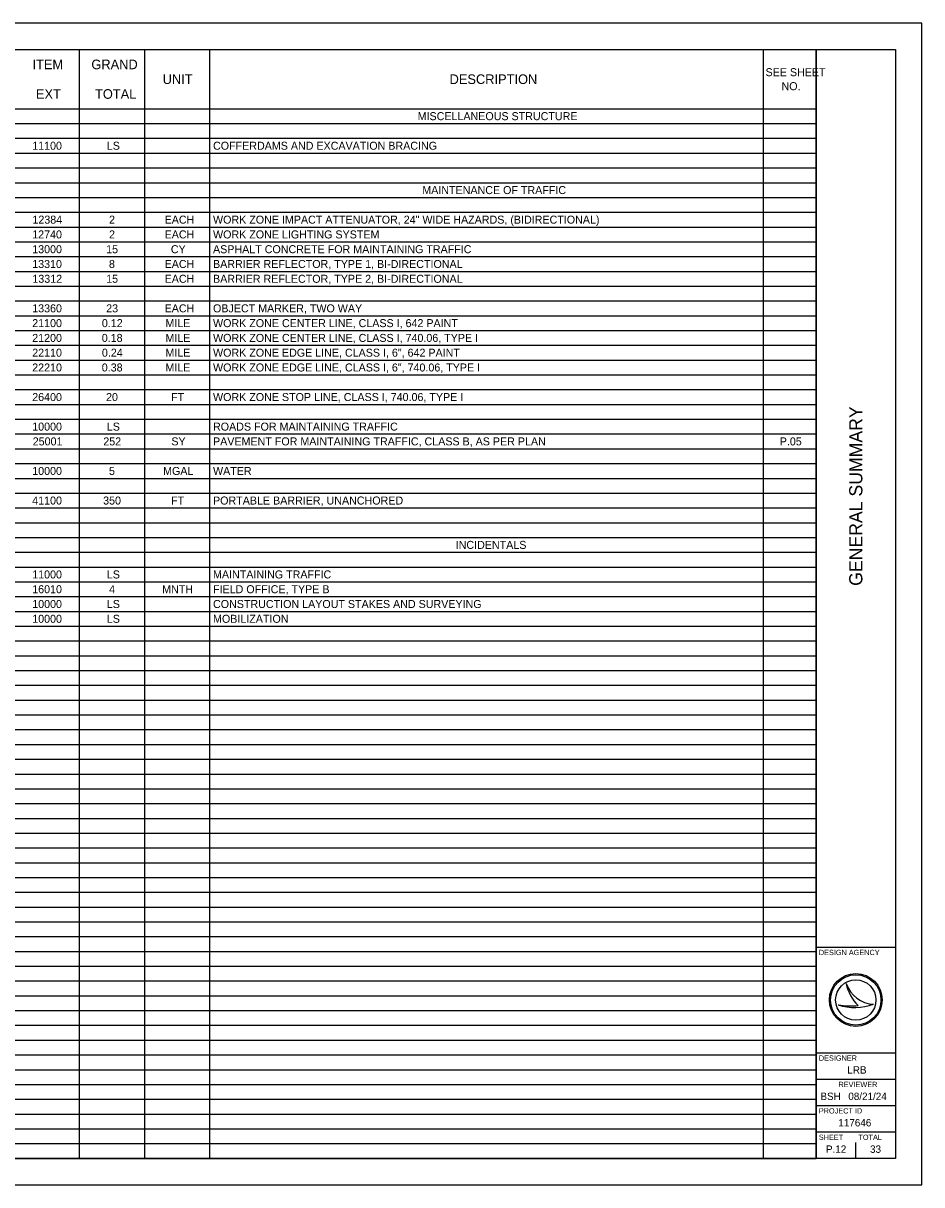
# Model space of a CAD drawing. Extents: x 0 to 34, y 0 to 22.
# Drawn here: x 16.97 to 34, y 0 to 22 of the extents above; entities that cross this region are included whole.
import ezdxf

# ---------------------------------------------------------------- set-up
doc = ezdxf.new("R2010")
doc.units = 0
for name, color, linetype in [('Default', 7, 'Continuous'), ('SH_Border', 7, 'Continuous'), ('SH_Cut_Line', 7, 'Continuous'), ('SH_Data', 7, 'Continuous')]:
    doc.layers.add(name, color=color, linetype=linetype)

msp = doc.modelspace()

# ---------------------------------------------------------------- linework, layer by layer
at = {"layer": 'Default'}
for p, q in [((1.5, 21.5), (32, 21.5)), ((18.035, 21.5), (18.035, 0.5)), ((19.27, 21.5), (19.27, 0.5)), ((20.505, 21.5), (20.505, 0.5)), ((30.995, 21.5), (30.995, 0.5)), ((32, 21.5), (32, 0.5)), ((1.5, 20.38), (32, 20.38)), ((1.5, 20.1), (32, 20.1)), ((1.5, 19.82), (32, 19.82)), ((1.5, 19.54), (32, 19.54)), ((1.5, 19.26), (32, 19.26)), ((1.5, 18.98), (32, 18.98)), ((1.5, 18.7), (32, 18.7)), ((1.5, 18.42), (32, 18.42)), ((1.5, 18.14), (32, 18.14)), ((1.5, 17.86), (32, 17.86)), ((1.5, 17.58), (32, 17.58)), ((1.5, 17.3), (32, 17.3)), ((1.5, 17.02), (32, 17.02)), ((1.5, 16.74), (32, 16.74)), ((1.5, 16.46), (32, 16.46)), ((1.5, 16.18), (32, 16.18)), ((1.5, 15.9), (32, 15.9)), ((1.5, 15.62), (32, 15.62)), ((1.5, 15.34), (32, 15.34)), ((1.5, 15.06), (32, 15.06)), ((1.5, 14.78), (32, 14.78)), ((1.5, 14.5), (32, 14.5)), ((1.5, 14.22), (32, 14.22)), ((1.5, 13.94), (32, 13.94)), ((1.5, 13.66), (32, 13.66)), ((1.5, 13.38), (32, 13.38)), ((1.5, 13.1), (32, 13.1)), ((1.5, 12.82), (32, 12.82)), ((1.5, 12.54), (32, 12.54)), ((1.5, 12.26), (32, 12.26)), ((1.5, 11.98), (32, 11.98)), ((1.5, 11.7), (32, 11.7)), ((1.5, 11.42), (32, 11.42)), ((1.5, 11.14), (32, 11.14)), ((1.5, 10.86), (32, 10.86)), ((1.5, 10.58), (32, 10.58)), ((1.5, 10.3), (32, 10.3)), ((1.5, 10.02), (32, 10.02)), ((1.5, 9.74), (32, 9.74)), ((1.5, 9.46), (32, 9.46)), ((1.5, 9.18), (32, 9.18)), ((1.5, 8.9), (32, 8.9)), ((1.5, 8.62), (32, 8.62)), ((1.5, 8.34), (32, 8.34)), ((1.5, 8.06), (32, 8.06)), ((1.5, 7.78), (32, 7.78)), ((1.5, 7.5), (32, 7.5)), ((1.5, 7.22), (32, 7.22)), ((1.5, 6.94), (32, 6.94)), ((1.5, 6.66), (32, 6.66)), ((1.5, 6.38), (32, 6.38)), ((1.5, 6.1), (32, 6.1)), ((1.5, 5.82), (32, 5.82)), ((1.5, 5.54), (32, 5.54)), ((1.5, 5.26), (32, 5.26)), ((1.5, 4.98), (32, 4.98)), ((1.5, 4.7), (32, 4.7)), ((1.5, 4.42), (32, 4.42)), ((1.5, 4.14), (32, 4.14)), ((1.5, 3.86), (32, 3.86)), ((1.5, 3.58), (32, 3.58)), ((1.5, 3.3), (32, 3.3)), ((1.5, 3.02), (32, 3.02)), ((1.5, 2.74), (32, 2.74)), ((1.5, 2.46), (32, 2.46)), ((1.5, 2.18), (32, 2.18)), ((1.5, 1.9), (32, 1.9)), ((1.5, 1.62), (32, 1.62)), ((1.5, 1.34), (32, 1.34)), ((1.5, 1.06), (32, 1.06)), ((1.5, 0.78), (32, 0.78)), ((1.5, 0.5), (32, 0.5))]:
    msp.add_line(p, q, dxfattribs=at)
at = {"layer": 'SH_Border'}
for p, q in [((32, 0.5), (32, 21.5)), ((32, 4.5), (33.5, 4.5)), ((32, 2.5), (33.5, 2.5)), ((32, 2), (33.5, 2)), ((32, 1.5), (33.5, 1.5)), ((32, 1), (33.5, 1))]:
    msp.add_line(p, q, dxfattribs=at)
msp.add_lwpolyline([(1.5, 21.5), (33.5, 21.5), (33.5, 0.5), (1.5, 0.5)], close=True, dxfattribs=at)
at = {"layer": 'SH_Cut_Line'}
msp.add_lwpolyline([(0, 0), (34, 0), (34, 22), (0, 22)], close=True, dxfattribs=at)
at = {"layer": 'SH_Data'}
for p, q in [((32.567, 3.81), (32.567, 3.81)), ((32.417, 3.41), (32.417, 3.41)), ((32.75, 3.5), (32.75, 3.5)), ((33.087, 3.419), (33.087, 3.419)), ((32.375, 0.675), (32.375, 0.675)), ((32.75, 0.5), (32.75, 0.8))]:
    msp.add_line(p, q, dxfattribs=at)
for radius in [0.5, 0.477, 0.477, 0.382]:
    msp.add_circle((32.75, 3.5), radius, dxfattribs=at)
for centre, radius, start, end in [((33.116, 3.998), 0.58, 198.9257, 198.9319), ((33.347, 3.97), 0.796, 191.6379, 191.6421), ((33.116, 3.998), 0.58, 198.9319, 267.1657), ((33.347, 3.97), 0.796, 191.6421, 226.0947), ((32.739, 4.37), 1.013, 251.4576, 290.0832), ((32.648, 4.654), 1.266, 259.4964, 259.4995), ((32.739, 4.37), 1.013, 251.4527, 251.4576), ((32.648, 4.654), 1.266, 259.4995, 276.6672)]:
    msp.add_arc(centre, radius, start, end, dxfattribs=at)

# ---------------------------------------------------------------- texts
at = {"layer": 'Default'}
for s, height, p in [('ITEM', 0.1818, (17.15, 21.129)), ('GRAND', 0.1818, (18.266, 21.129)), ('SEE SHEET ', 0.1515, (31.04, 20.997)), ('UNIT', 0.1818, (19.617, 20.849)), ('DESCRIPTION', 0.18184, (25.053, 20.849)), ('EXT', 0.1818, (17.215, 20.569)), ('TOTAL', 0.1818, (18.335, 20.569)), ('NO.', 0.1515, (31.342, 20.732)), ('MISCELLANEOUS STRUCTURE', 0.15153, (24.448, 20.164)), ('11100', 0.1515, (17.145, 19.604)), ('LS', 0.1515, (18.559, 19.604)), ('COFFERDAMS AND EXCAVATION BRACING', 0.15153, (20.571, 19.604)), ('MAINTENANCE OF TRAFFIC', 0.15153, (24.536, 18.764)), ('12384', 0.1515, (17.149, 18.204)), ('2', 0.152, (18.601, 18.204)), ('EACH', 0.1515, (19.654, 18.204)), ('WORK ZONE IMPACT ATTENUATOR, 24" WIDE HAZARDS, (BIDIRECTIONAL)', 0.15153, (20.571, 18.204)), ('12740', 0.1515, (17.145, 17.924)), ('2', 0.152, (18.601, 17.924)), ('EACH', 0.1515, (19.654, 17.924)), ('WORK ZONE LIGHTING SYSTEM', 0.15153, (20.571, 17.924)), ('13000', 0.1515, (17.145, 17.644)), ('15', 0.1515, (18.546, 17.644)), ('CY', 0.1515, (19.772, 17.644)), ('ASPHALT CONCRETE FOR MAINTAINING TRAFFIC', 0.15153, (20.571, 17.644)), ('13310', 0.1515, (17.145, 17.364)), ('8', 0.152, (18.599, 17.364)), ('EACH', 0.1515, (19.654, 17.364)), ('BARRIER REFLECTOR, TYPE 1, BI-DIRECTIONAL', 0.15153, (20.571, 17.364)), ('13312', 0.1515, (17.148, 17.084)), ('15', 0.1515, (18.546, 17.084)), ('EACH', 0.1515, (19.654, 17.084)), ('BARRIER REFLECTOR, TYPE 2, BI-DIRECTIONAL', 0.15153, (20.571, 17.084)), ('13360', 0.1515, (17.145, 16.524)), ('23', 0.1515, (18.547, 16.524)), ('EACH', 0.1515, (19.654, 16.524)), ('OBJECT MARKER, TWO WAY', 0.15153, (20.571, 16.524)), ('21100', 0.1515, (17.145, 16.244)), ('0.12', 0.1515, (18.465, 16.244)), ('MILE', 0.1515, (19.669, 16.244)), ('WORK ZONE CENTER LINE, CLASS I, 642 PAINT', 0.15153, (20.571, 16.244)), ('21200', 0.1515, (17.145, 15.964)), ('0.18', 0.1515, (18.463, 15.964)), ('MILE', 0.1515, (19.669, 15.964)), ('WORK ZONE CENTER LINE, CLASS I, 740.06, TYPE I', 0.15153, (20.571, 15.964)), ('22110', 0.1515, (17.145, 15.684)), ('0.24', 0.1515, (18.466, 15.684)), ('MILE', 0.1515, (19.669, 15.684)), ('WORK ZONE EDGE LINE, CLASS I, 6", 642 PAINT', 0.15153, (20.571, 15.684)), ('22210', 0.1515, (17.145, 15.404)), ('0.38', 0.1515, (18.463, 15.404)), ('MILE', 0.1515, (19.669, 15.404)), ('WORK ZONE EDGE LINE, CLASS I, 6", 740.06, TYPE I', 0.15153, (20.571, 15.404)), ('26400', 0.1515, (17.145, 14.844)), ('20', 0.1515, (18.544, 14.844)), ('FT', 0.1515, (19.778, 14.844)), ('WORK ZONE STOP LINE, CLASS I, 740.06, TYPE I', 0.15153, (20.571, 14.844)), ('10000', 0.1515, (17.145, 14.284)), ('LS', 0.1515, (18.559, 14.284)), ('ROADS FOR MAINTAINING TRAFFIC', 0.15153, (20.571, 14.284)), ('25001', 0.1515, (17.155, 14.004)), ('252', 0.1515, (18.492, 14.004)), ('SY', 0.1515, (19.781, 14.004)), ('PAVEMENT FOR MAINTAINING TRAFFIC, CLASS B, AS PER PLAN', 0.15153, (20.571, 14.004)), ('P.05', 0.1515, (31.309, 14.004)), ('10000', 0.1515, (17.145, 13.444)), ('5', 0.152, (18.6, 13.444)), ('MGAL', 0.1515, (19.625, 13.444)), ('WATER', 0.1515, (20.571, 13.444)), ('41100', 0.1515, (17.145, 12.884)), ('350', 0.1515, (18.489, 12.884)), ('FT', 0.1515, (19.778, 12.884)), ('PORTABLE BARRIER, UNANCHORED', 0.15153, (20.571, 12.884)), ('INCIDENTALS', 0.15153, (25.169, 12.044)), ('11000', 0.1515, (17.145, 11.484)), ('LS', 0.1515, (18.559, 11.484)), ('MAINTAINING TRAFFIC', 0.15153, (20.571, 11.484)), ('16010', 0.1515, (17.145, 11.204)), ('4', 0.152, (18.602, 11.204)), ('MNTH', 0.1515, (19.607, 11.204)), ('FIELD OFFICE, TYPE B', 0.15153, (20.571, 11.204)), ('10000', 0.1515, (17.145, 10.924)), ('LS', 0.1515, (18.559, 10.924)), ('CONSTRUCTION LAYOUT STAKES AND SURVEYING', 0.15153, (20.571, 10.924)), ('10000', 0.1515, (17.145, 10.644)), ('LS', 0.1515, (18.559, 10.644)), ('MOBILIZATION', 0.15153, (20.571, 10.644))]:
    msp.add_text(s, height=height, dxfattribs=at).set_placement(p)
at = {"layer": 'SH_Data'}
msp.add_text('GENERAL SUMMARY', height=0.25, rotation=90, dxfattribs=at).set_placement((32.875, 11.344))
for s, height, p in [('DESIGN AGENCY', 0.1, (32.05, 4.35)), ('DESIGNER', 0.1, (32.05, 2.35)), ('LRB', 0.14, (32.589, 2.105)), ('REVIEWER', 0.1, (32.422, 1.85)), ('BSH', 0.14, (32.08, 1.605)), ('08/21/24', 0.14, (32.608, 1.605)), ('PROJECT ID', 0.1, (32.05, 1.35)), ('117646', 0.14, (32.419, 1.105)), ('SHEET', 0.1, (32.05, 0.85)), ('TOTAL', 0.1, (32.8, 0.85)), ('P.12', 0.14, (32.185, 0.605)), ('33', 0.14, (33.02, 0.605))]:
    msp.add_text(s, height=height, dxfattribs=at).set_placement(p)

doc.saveas('drawing.dxf')
